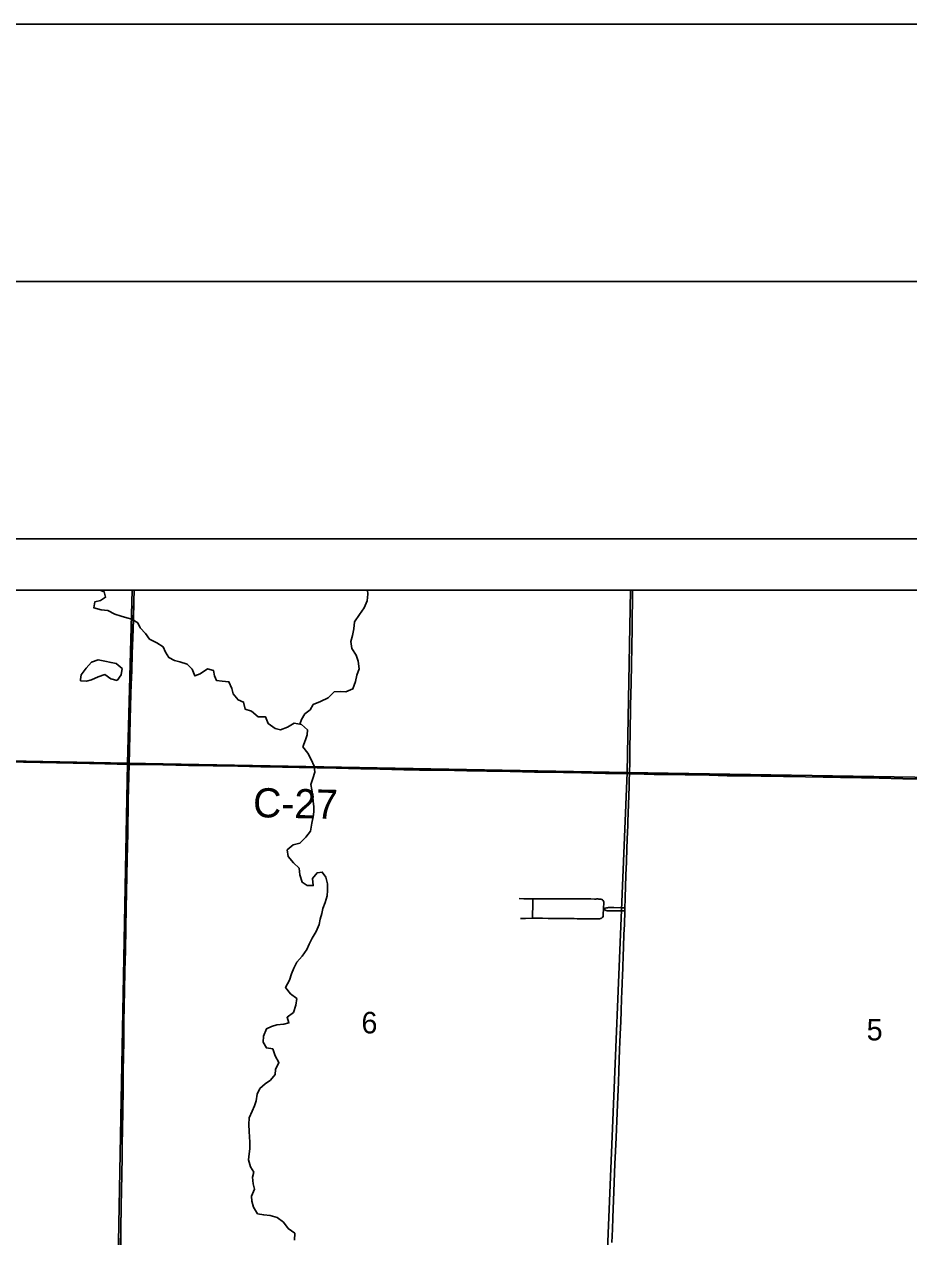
# Model space of a CAD drawing. Extents: x 0 to 34, y 0 to 22.
# Drawn here: x 5.615 to 7.336, y 19.643 to 22 of the extents above; entities that cross this region are included whole.
import ezdxf

# ---------------------------------------------------------------- set-up
doc = ezdxf.new("R2010")
doc.units = 0
for name, color, linetype in [('GM_X_Corporation', 7, 'Continuous'), ('GM_X_County_Road', 7, 'Continuous'), ('GM_X_County_Road_Text', 7, 'Continuous'), ('GM_X_Minor_Lake', 7, 'Continuous'), ('GM_X_Minor_River', 7, 'Continuous'), ('GM_X_Section_Text', 7, 'Continuous'), ('GM_X_State_Route', 7, 'Continuous'), ('GM_X_Township_Road', 7, 'Continuous'), ('SH_Border', 7, 'Continuous'), ('SH_Cut_Line', 7, 'Continuous'), ('SH_Data', 7, 'Continuous')]:
    doc.layers.add(name, color=color, linetype=linetype)

msp = doc.modelspace()

# ---------------------------------------------------------------- linework, layer by layer
at = {"layer": 'GM_X_Corporation'}
for points in [[(8.9, 14.4942), (8.9, 20.9), (2.1, 20.9)], [(5.5822, 20.5668), (5.742, 20.5637), (5.7718, 20.563), (5.8191, 20.5619), (5.8206, 20.6191), (5.8215, 20.6496), (5.8222, 20.6738), (5.8229, 20.6987), (5.8234, 20.7173), (5.8241, 20.744), (5.8253, 20.777), (5.8262, 20.808), (5.8275, 20.8428), (5.8286, 20.8789), (5.8292, 20.9), (2.1, 20.9)], [(8.9, 20.9), (5.8292, 20.9), (5.8286, 20.8789), (5.8275, 20.8428), (5.8262, 20.808), (5.8253, 20.777), (5.8241, 20.744), (5.8234, 20.7173), (5.8229, 20.6987), (5.8222, 20.6738), (5.8215, 20.6496), (5.8206, 20.6191), (5.8191, 20.5619), (5.8338, 20.5618), (5.8518, 20.5614), (5.8849, 20.5607), (5.9347, 20.5598), (6.0307, 20.5582), (6.0755, 20.5574), (6.1177, 20.5565), (6.1501, 20.5559), (6.1849, 20.555), (6.2222, 20.5542), (6.27, 20.5531), (6.3068, 20.5523), (6.3532, 20.5514), (6.3841, 20.5509), (6.428, 20.5504), (6.4759, 20.5495), (6.515, 20.5488), (6.5604, 20.5478), (6.6077, 20.5469), (6.6643, 20.5459), (6.6991, 20.5452), (6.7457, 20.5442), (6.7923, 20.5435), (6.8011, 20.5432), (6.8405, 20.5421), (6.9009, 20.5413), (6.9475, 20.5405), (6.9823, 20.5398), (7.0065, 20.5394), (7.0482, 20.5392), (7.1346, 20.5373), (7.2024, 20.5364), (7.2434, 20.5355), (7.2776, 20.5349), (7.3242, 20.5339), (7.3683, 20.5332)], [(5.8023, 19.5887), (5.8033, 19.6582), (5.804, 19.7029), (5.805, 19.7645), (5.8056, 19.798), (5.8059, 19.826), (5.8061, 19.8484), (5.8068, 19.8913), (5.8074, 19.9273), (5.8078, 19.9659), (5.8087, 20.0225), (5.8092, 20.061), (5.8104, 20.1219), (5.8111, 20.1605), (5.812, 20.1996), (5.8128, 20.2438), (5.8136, 20.2817), (5.8142, 20.3134), (5.8157, 20.3774), (5.8165, 20.4284), (5.8177, 20.4924), (5.8191, 20.5619), (5.7718, 20.563), (5.742, 20.5637), (5.5822, 20.5668)], [(7.3683, 20.5332), (7.3242, 20.5339), (7.2776, 20.5349), (7.2434, 20.5355), (7.2024, 20.5364), (7.1346, 20.5373), (7.0482, 20.5392), (7.0065, 20.5394), (6.9823, 20.5398), (6.9475, 20.5405), (6.9009, 20.5413), (6.8405, 20.5421), (6.8011, 20.5432), (6.7923, 20.5435), (6.7457, 20.5442), (6.6991, 20.5452), (6.6643, 20.5459), (6.6077, 20.5469), (6.5604, 20.5478), (6.515, 20.5488), (6.4759, 20.5495), (6.428, 20.5504), (6.3841, 20.5509), (6.3532, 20.5514), (6.3068, 20.5523), (6.27, 20.5531), (6.2222, 20.5542), (6.1849, 20.555), (6.1501, 20.5559), (6.1177, 20.5565), (6.0755, 20.5574), (6.0307, 20.5582), (5.9347, 20.5598), (5.8849, 20.5607), (5.8518, 20.5614), (5.8338, 20.5618), (5.8191, 20.5619), (5.8177, 20.4924), (5.8165, 20.4284), (5.8157, 20.3774), (5.8142, 20.3134), (5.8136, 20.2817), (5.8128, 20.2438), (5.812, 20.1996), (5.8111, 20.1605), (5.8104, 20.1219), (5.8092, 20.061), (5.8087, 20.0225), (5.8078, 19.9659), (5.8074, 19.9273), (5.8068, 19.8913), (5.8061, 19.8484), (5.8059, 19.826), (5.8056, 19.798), (5.805, 19.7645), (5.804, 19.7029), (5.8033, 19.6582), (5.8023, 19.5887)]]:
    msp.add_lwpolyline(points, dxfattribs=at)
for points in [[(5.8254, 20.9), (4.8189, 20.9), (4.8123, 20.5837), (4.829, 20.5833), (5.8164, 20.5638)], [(6.7947, 20.9), (5.8254, 20.9), (5.8164, 20.5638), (6.788, 20.5454)], [(7.7966, 20.9), (6.7947, 20.9), (6.788, 20.5454), (7.7872, 20.529)], [(4.829, 20.5833), (5.8164, 20.5638), (5.7981, 19.5979), (5.7974, 19.5584), (4.8036, 19.5906)], [(5.8164, 20.5638), (6.788, 20.5454), (6.7486, 19.5865), (6.7472, 19.5762), (5.7981, 19.5979)], [(6.788, 20.5454), (7.7872, 20.529), (7.7504, 19.5655), (6.7486, 19.5865)]]:
    msp.add_lwpolyline(points, close=True, dxfattribs=at)
at = {"layer": 'GM_X_County_Road'}
for points in [[(5.8193, 20.5613), (5.8209, 20.6186), (5.8218, 20.649), (5.8224, 20.6733), (5.8231, 20.6981), (5.8236, 20.7168), (5.8244, 20.7435), (5.8255, 20.7764), (5.8265, 20.8075), (5.8277, 20.8423), (5.8289, 20.8783), (5.8294, 20.9)], [(4.8317, 20.5803), (4.8631, 20.5797), (4.9371, 20.5783), (4.9881, 20.5772), (5.0372, 20.5763), (5.0962, 20.5752), (5.1839, 20.5733), (5.2417, 20.5725), (5.2989, 20.5715), (5.3642, 20.5703), (5.445, 20.5691), (5.4811, 20.5682), (5.5445, 20.5669), (5.5824, 20.5662), (5.7422, 20.5631), (5.7721, 20.5624), (5.8193, 20.5613)], [(5.8025, 19.5881), (5.8035, 19.6576), (5.8043, 19.7024), (5.8052, 19.7639), (5.8058, 19.7975), (5.8061, 19.8255), (5.8063, 19.8478), (5.8071, 19.8907), (5.8076, 19.9268), (5.808, 19.9653), (5.8089, 20.0219), (5.8094, 20.0605), (5.8106, 20.1214), (5.8113, 20.1599), (5.8122, 20.1991), (5.813, 20.2432), (5.8138, 20.2811), (5.8144, 20.3128), (5.8159, 20.3769), (5.8167, 20.4278), (5.8179, 20.4919), (5.8193, 20.5613)], [(5.8193, 20.5613), (5.8341, 20.5613), (5.8521, 20.5608), (5.8852, 20.5601), (5.935, 20.5592), (6.0309, 20.5577), (6.0757, 20.5568), (6.118, 20.5559), (6.1503, 20.5553), (6.1851, 20.5545), (6.2224, 20.5536), (6.2702, 20.5526), (6.307, 20.5518), (6.3534, 20.5509), (6.3843, 20.5503), (6.4282, 20.5498), (6.4761, 20.5489), (6.5153, 20.5482), (6.5606, 20.5472), (6.6079, 20.5463), (6.6645, 20.5454), (6.6993, 20.5447), (6.7459, 20.5437), (6.7925, 20.5429)], [(6.7925, 20.5429), (6.8013, 20.5426), (6.8408, 20.5416), (6.9011, 20.5408), (6.9477, 20.54), (6.9825, 20.5393), (7.0068, 20.5388), (7.0484, 20.5386), (7.1348, 20.5368), (7.2026, 20.5358), (7.2436, 20.5349), (7.2778, 20.5343), (7.3244, 20.5333), (7.3686, 20.5327), (7.4463, 20.5313), (7.5041, 20.5303), (7.56, 20.5292), (7.6098, 20.5286), (7.6614, 20.528), (7.6825, 20.5275), (7.7285, 20.5265), (7.7826, 20.5255), (7.7917, 20.5253)]]:
    msp.add_lwpolyline(points, dxfattribs=at)
at = {"layer": 'GM_X_Minor_Lake'}
for points in [[(5.796, 20.724), (5.8041, 20.7353), (5.8059, 20.7474), (5.7943, 20.7571), (5.7845, 20.7592), (5.772, 20.7621), (5.7592, 20.7646), (5.7466, 20.7599), (5.7357, 20.748), (5.7264, 20.7356), (5.7252, 20.726)], [(5.7252, 20.726), (5.725, 20.7239), (5.7368, 20.7229), (5.7463, 20.7258), (5.7593, 20.7316), (5.7719, 20.7359), (5.7839, 20.7273), (5.796, 20.724)]]:
    msp.add_lwpolyline(points, dxfattribs=at)
at = {"layer": 'GM_X_Minor_River'}
for points in [[(6.1573, 20.5953), (6.1622, 20.6089), (6.1655, 20.6187), (6.1661, 20.6281), (6.1546, 20.6387), (6.1406, 20.6413), (6.1275, 20.6333), (6.1141, 20.6287), (6.1036, 20.6312), (6.0898, 20.6407), (6.0848, 20.6534), (6.0707, 20.6537), (6.0573, 20.6647), (6.0453, 20.6684), (6.0422, 20.6822), (6.0313, 20.687), (6.0217, 20.6983), (6.0193, 20.709), (6.0136, 20.722), (6.0003, 20.7231), (5.9897, 20.7241), (5.9858, 20.7337), (5.9837, 20.7437), (5.9717, 20.747), (5.9578, 20.7375), (5.9471, 20.7332), (5.9421, 20.7466), (5.9321, 20.756), (5.9178, 20.7609), (5.9079, 20.7634), (5.8967, 20.7687), (5.8905, 20.7791), (5.8854, 20.7895), (5.8731, 20.7974), (5.8592, 20.8046), (5.8515, 20.8154), (5.8412, 20.827), (5.8361, 20.8367), (5.8245, 20.8434), (5.8147, 20.8463), (5.8038, 20.8496), (5.7914, 20.8534), (5.7779, 20.8605), (5.7654, 20.8616), (5.7511, 20.8654), (5.7529, 20.8775), (5.7639, 20.8799), (5.7736, 20.8861), (5.7712, 20.8964), (5.7625, 20.9)], [(6.1515, 20.6393), (6.1545, 20.6486), (6.1612, 20.6594), (6.1716, 20.6675), (6.1776, 20.6776), (6.1914, 20.6833), (6.2064, 20.6906), (6.2184, 20.702), (6.231, 20.7032), (6.2408, 20.7026), (6.2542, 20.708), (6.2595, 20.7226), (6.2625, 20.7347), (6.2666, 20.7468), (6.265, 20.7616), (6.2611, 20.7735), (6.2527, 20.7866), (6.2508, 20.8), (6.2538, 20.8121), (6.2567, 20.8249), (6.2578, 20.8386), (6.2676, 20.8524), (6.2767, 20.8658), (6.2823, 20.879), (6.2834, 20.8922), (6.283, 20.9)], [(6.1409, 19.6361), (6.1416, 19.6498), (6.1286, 19.6592), (6.1198, 19.6712), (6.1075, 19.6807), (6.0939, 19.684), (6.0814, 19.6855), (6.0693, 19.6877), (6.0613, 19.7008), (6.0578, 19.7123), (6.0577, 19.7222), (6.0633, 19.7357), (6.0605, 19.746), (6.0593, 19.759), (6.0618, 19.7688), (6.0556, 19.7788), (6.0518, 19.7926), (6.0528, 19.8044), (6.0539, 19.8142), (6.0542, 19.8271), (6.0537, 19.837), (6.0528, 19.8477), (6.052, 19.8614), (6.0531, 19.8743), (6.0587, 19.887), (6.0631, 19.8972), (6.0664, 19.907), (6.0686, 19.9202), (6.0738, 19.9311), (6.0843, 19.94), (6.0943, 19.9477), (6.1037, 19.9585), (6.1043, 19.9683), (6.1107, 19.9818), (6.1035, 19.9949), (6.0989, 20.0083), (6.0864, 20.0102), (6.0802, 20.0214), (6.0809, 20.0331), (6.0865, 20.047), (6.0961, 20.0517), (6.1068, 20.0552), (6.1205, 20.0564), (6.1301, 20.0588), (6.1266, 20.0696), (6.1393, 20.0791), (6.1438, 20.0934), (6.1453, 20.1059), (6.133, 20.1154), (6.1238, 20.1274), (6.1314, 20.1416), (6.1355, 20.1541), (6.1395, 20.165), (6.1455, 20.177), (6.156, 20.1885), (6.1651, 20.2016), (6.1699, 20.2117), (6.1755, 20.2233), (6.1834, 20.2364), (6.1891, 20.25), (6.1912, 20.2605), (6.1941, 20.2711), (6.1963, 20.2809), (6.2004, 20.2926), (6.2045, 20.3058), (6.2055, 20.316), (6.2054, 20.3293), (6.202, 20.3423), (6.195, 20.352), (6.1851, 20.3503), (6.1761, 20.3396), (6.1776, 20.3255), (6.1659, 20.3261), (6.1558, 20.3321), (6.1512, 20.3463), (6.15, 20.3592), (6.1393, 20.3701), (6.1289, 20.3825), (6.1266, 20.3951), (6.1382, 20.4047), (6.1516, 20.4078), (6.1629, 20.4197), (6.1723, 20.4316), (6.1749, 20.4471), (6.1771, 20.4592), (6.1789, 20.469), (6.1788, 20.4793), (6.1775, 20.4888), (6.1766, 20.4983), (6.1746, 20.5117), (6.173, 20.522), (6.1767, 20.534), (6.1808, 20.5461), (6.1796, 20.5579), (6.1738, 20.571), (6.1669, 20.5833), (6.1573, 20.5953)]]:
    msp.add_lwpolyline(points, dxfattribs=at)
at = {"layer": 'GM_X_State_Route'}
for points in [[(6.7987, 20.9), (6.7975, 20.8253), (6.7957, 20.7196), (6.7948, 20.6748), (6.7937, 20.6213), (6.7932, 20.5946), (6.7929, 20.5629), (6.7926, 20.5474), (6.7925, 20.5429)], [(6.7925, 20.5429), (6.7923, 20.539), (6.7922, 20.5351), (6.792, 20.5309), (6.7916, 20.5185), (6.7908, 20.4831), (6.7896, 20.4502), (6.7894, 20.4427), (6.7893, 20.4409), (6.7888, 20.4309), (6.7876, 20.3986), (6.7865, 20.3719), (6.7861, 20.3582), (6.7856, 20.3471), (6.7848, 20.3222), (6.7842, 20.3042), (6.7839, 20.2943), (6.7837, 20.2876), (6.7835, 20.2826), (6.7834, 20.2787), (6.7833, 20.2764), (6.7826, 20.2501), (6.7817, 20.2303), (6.7814, 20.2235), (6.781, 20.2135), (6.7806, 20.2036), (6.7803, 20.1911), (6.78, 20.1812), (6.7798, 20.175), (6.7795, 20.1644), (6.7791, 20.152), (6.7785, 20.1352), (6.7779, 20.1191), (6.7773, 20.106), (6.7764, 20.0818), (6.7755, 20.0613), (6.7745, 20.0371), (6.7738, 20.0203), (6.7734, 20.0078), (6.7718, 19.9656), (6.771, 19.9432), (6.7691, 19.9003), (6.7664, 19.8357), (6.7653, 19.8096), (6.7643, 19.7848), (6.7619, 19.7307), (6.76, 19.6798), (6.7593, 19.658), (6.7583, 19.6319)]]:
    msp.add_lwpolyline(points, dxfattribs=at)
at = {"layer": 'GM_X_Township_Road'}
for points in [[(6.6047, 20.2998), (6.5944, 20.2999), (6.5869, 20.3001), (6.5783, 20.3003)], [(6.6038, 20.262), (6.6039, 20.2654), (6.6042, 20.2741), (6.6043, 20.281), (6.6045, 20.2883), (6.6047, 20.2939), (6.6047, 20.2998)], [(6.7419, 20.2802), (6.7421, 20.2836), (6.7426, 20.2904), (6.7425, 20.2935), (6.7421, 20.2953), (6.7416, 20.2965), (6.7409, 20.2974), (6.7399, 20.2981), (6.7389, 20.2987), (6.7371, 20.299), (6.7356, 20.2992), (6.7329, 20.2995), (6.7311, 20.2996), (6.7288, 20.2996), (6.7271, 20.2995), (6.7253, 20.2995), (6.7242, 20.2995), (6.7176, 20.2997), (6.7108, 20.2997), (6.7055, 20.2996), (6.7003, 20.2996), (6.6909, 20.2996), (6.6859, 20.2996), (6.6754, 20.2998), (6.6666, 20.2997), (6.659, 20.2997), (6.649, 20.2998), (6.642, 20.2997), (6.635, 20.2997), (6.6247, 20.2997), (6.6093, 20.2997), (6.6047, 20.2998)], [(6.6038, 20.262), (6.6109, 20.262), (6.6232, 20.262), (6.6344, 20.2619), (6.6409, 20.2619), (6.6534, 20.2617), (6.6632, 20.2616), (6.6687, 20.2616), (6.6751, 20.2615), (6.6795, 20.2615), (6.6852, 20.2614), (6.6909, 20.2613), (6.6993, 20.2613), (6.7062, 20.2612), (6.7167, 20.2612), (6.7285, 20.2611), (6.7344, 20.2612), (6.7362, 20.2614), (6.7374, 20.2618), (6.7384, 20.2624), (6.7396, 20.2635), (6.7404, 20.2645), (6.7411, 20.2662), (6.7414, 20.2681), (6.7416, 20.2718), (6.7417, 20.278), (6.7419, 20.2802)], [(6.7419, 20.2802), (6.7454, 20.2817), (6.7482, 20.2824), (6.7499, 20.2827), (6.7516, 20.283), (6.762, 20.2829), (6.776, 20.2827), (6.7835, 20.2826)], [(6.7419, 20.2802), (6.7436, 20.2789), (6.7459, 20.2778), (6.7471, 20.2772), (6.7489, 20.2768), (6.7515, 20.2766), (6.7567, 20.2766), (6.7649, 20.2765), (6.7773, 20.2764), (6.7833, 20.2764)], [(6.5808, 20.2617), (6.584, 20.2617), (6.5906, 20.2619), (6.6038, 20.262)]]:
    msp.add_lwpolyline(points, dxfattribs=at)
at = {"layer": 'SH_Border'}
msp.add_lwpolyline([(1.5, 21.5), (33.5, 21.5), (33.5, 0.5), (1.5, 0.5)], close=True, dxfattribs=at)
at = {"layer": 'SH_Cut_Line'}
msp.add_lwpolyline([(0, 0), (34, 0), (34, 22), (0, 22)], close=True, dxfattribs=at)
at = {"layer": 'SH_Data'}
for p, q in [((2, 21), (9, 21)), ((2.1, 20.9), (8.9, 20.9))]:
    msp.add_line(p, q, dxfattribs=at)

# ---------------------------------------------------------------- texts
at = {"layer": 'GM_X_County_Road_Text'}
msp.add_text('C-27', height=0.05682, rotation=358.6275, dxfattribs=at).set_placement((6.06, 20.4588))
at = {"layer": 'GM_X_Section_Text'}
for s, p in [('6', (6.2712, 20.0383)), ('5', (7.2537, 20.0247))]:
    msp.add_text(s, height=0.0419, rotation=0, dxfattribs=at).set_placement(p)

doc.saveas('drawing.dxf')
